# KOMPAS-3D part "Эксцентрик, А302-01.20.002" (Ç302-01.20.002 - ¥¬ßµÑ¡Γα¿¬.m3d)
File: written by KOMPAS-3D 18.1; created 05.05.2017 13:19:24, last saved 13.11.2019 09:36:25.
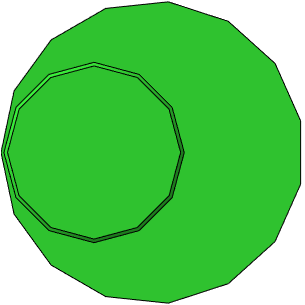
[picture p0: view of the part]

Document properties: Автор: Милов; Организация: Милов; Полное имя файла: D:\Мембранные насосы\Мембранный электропривод\А302-00.00.000 - ASTRA-302 (МЭ200)\3Д ПВХ\А302-01.20.002 - Эксцентрик.m3d

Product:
- Part/product: Эксцентрик  | designation А302-01.20.002
    Материал: Сталь 40Х  ГОСТ 4543-71 (density 7825 kg/m3)
    Масса: 1.91612
    Раздел спецификации: Детали
    Форматы листов документа: A3
    source file: А302-01.20.002 - Эксцентрик.cdw
  - Component: Эксцентрик  | designation А302-01.20.002  | Масса: 1.91612; Раздел спецификации: Детали; Форматы листов документа: A3; source file: А302-01.20.002 - Эксцентрик.cdw

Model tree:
1. Эскиз:1
2. Операция выдавливания:1
     Расстояние 1 = 144.5
3. Эскиз:4  (with: Операция выдавливания:1)
4. Операция выдавливания:3
     Расстояние 1 = 29
5. Смещенная плоскость:1  (with: Операция выдавливания:3)
     Расстояние = 2.3
6. Эскиз:7  (with: Операция выдавливания:3)
7. Вырезать элемент выдавливания:4
     Расстояние 1 = 1.4
8. Фаска:1  (with: Операция выдавливания:3)
     Угол = 45; Длина 1 = 0.5; Длина 2 = 0.5
9. Массив по сетке:1  (with: Вырезать элемент выдавливания:4, Смещенная плоскость:1, Эскиз:7)  (2 pattern instances)
     Шаг 1 = 16.1; Угол раствора = 90
10. Эскиз:8  (with: Операция выдавливания:1)
11. Операция вращения:1
     Угол 1 = 360
12. Фаска:2  (with: Операция вращения:1)
     Угол = 45; Длина 1 = 1; Длина 2 = 1
13. Смещенная плоскость:2
     Расстояние = 8.5
14. Эскиз:9  (with: Операция вращения:1)
15. Вырезать элемент выдавливания:5
     Расстояние 2 = 4
16. Эскиз:10  (with: Операция выдавливания:1)
17. Вырезать элемент выдавливания:6  (with: Операция выдавливания:1)
     Расстояние 1 = 136.5; На расстояние 1 = 8
18. Эскиз:11  (with: Операция выдавливания:1, Операция вращения:1, Вырезать элемент выдавливания:6)
19. Вырезать элемент выдавливания:7  (with: Вырезать элемент выдавливания:6)
     Расстояние 1 = 106.5; На расстояние 1 = 30
20. Фаска:3  (with: Вырезать элемент выдавливания:7)
     Угол = 45; Длина 1 = 0.5; Длина 2 = 0.5
21. Смещенная плоскость:3  (with: Вырезать элемент выдавливания:6)
     Расстояние = 18
22. Эскиз:12  (with: Вырезать элемент выдавливания:6)
23. Вырезать элемент выдавливания:8
     Расстояние 2 = 1.85
24. Эскиз:13  (with: Операция выдавливания:3, Фаска:1)
25. Эскиз:14  (with: Операция выдавливания:3, Фаска:1)  (labels: Сталь 40Х  ГОСТ 4543-71)

Expressions: 25/2; 23.5/2; 112+1.3

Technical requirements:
  Gost Type A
